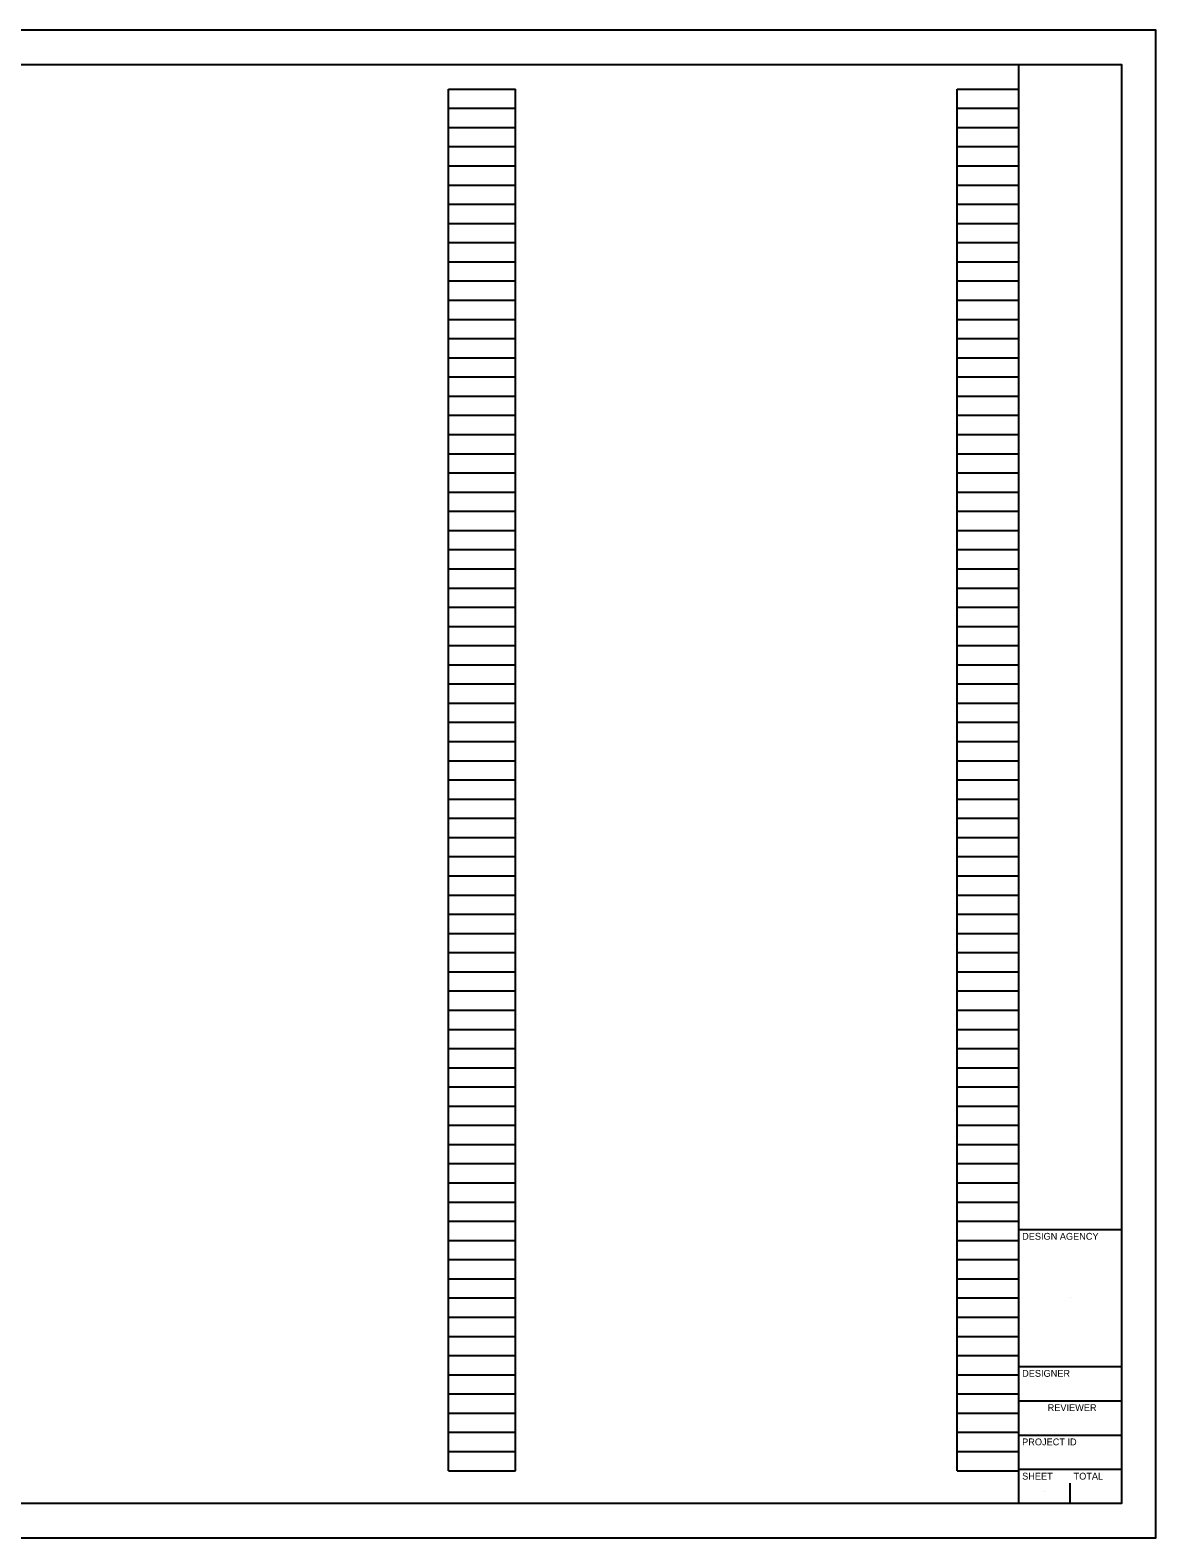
# Model space of a CAD drawing. Extents: x 0 to 34, y 0 to 22.
# Drawn here: x 17.58 to 34, y 0 to 22 of the extents above; entities that cross this region are included whole.
import ezdxf

# ---------------------------------------------------------------- set-up
doc = ezdxf.new("R2010")
doc.units = 0
doc.layers.add('SH_Border', color=7, linetype='Continuous')
doc.layers.add('SH_Data', color=7, linetype='Continuous')

msp = doc.modelspace()

# ---------------------------------------------------------------- linework, layer by layer
at = {"layer": 'SH_Border'}
for p, q in [((32, 0.5), (32, 21.5)), ((32, 4.5), (33.5, 4.5)), ((32, 2.5), (33.5, 2.5)), ((32, 2), (33.5, 2)), ((32, 1.5), (33.5, 1.5)), ((32, 1), (33.5, 1))]:
    msp.add_line(p, q, dxfattribs=at)
msp.add_lwpolyline([(1.5, 21.5), (33.5, 21.5), (33.5, 0.5), (1.5, 0.5)], close=True, dxfattribs=at)
at = {"layer": 'SH_Data'}
for p, q in [((23.68, 0.98), (23.68, 21.14)), ((23.68, 21.14), (24.66, 21.14)), ((24.66, 0.98), (24.66, 21.14)), ((31.1, 0.98), (31.1, 21.14)), ((31.1, 21.14), (32, 21.14)), ((32, 0.98), (32, 21.14)), ((23.68, 20.86), (24.66, 20.86)), ((31.1, 20.86), (32, 20.86)), ((23.68, 20.58), (24.66, 20.58)), ((31.1, 20.58), (32, 20.58)), ((23.68, 20.3), (24.66, 20.3)), ((31.1, 20.3), (32, 20.3)), ((23.68, 20.02), (24.66, 20.02)), ((31.1, 20.02), (32, 20.02)), ((23.68, 19.74), (24.66, 19.74)), ((31.1, 19.74), (32, 19.74)), ((23.68, 19.46), (24.66, 19.46)), ((31.1, 19.46), (32, 19.46)), ((23.68, 19.18), (24.66, 19.18)), ((31.1, 19.18), (32, 19.18)), ((23.68, 18.9), (24.66, 18.9)), ((31.1, 18.9), (32, 18.9)), ((23.68, 18.62), (24.66, 18.62)), ((31.1, 18.62), (32, 18.62)), ((23.68, 18.34), (24.66, 18.34)), ((31.1, 18.34), (32, 18.34)), ((23.68, 18.06), (24.66, 18.06)), ((31.1, 18.06), (32, 18.06)), ((23.68, 17.78), (24.66, 17.78)), ((31.1, 17.78), (32, 17.78)), ((23.68, 17.5), (24.66, 17.5)), ((31.1, 17.5), (32, 17.5)), ((23.68, 17.22), (24.66, 17.22)), ((31.1, 17.22), (32, 17.22)), ((23.68, 16.94), (24.66, 16.94)), ((31.1, 16.94), (32, 16.94)), ((23.68, 16.66), (24.66, 16.66)), ((31.1, 16.66), (32, 16.66)), ((23.68, 16.38), (24.66, 16.38)), ((31.1, 16.38), (32, 16.38)), ((23.68, 16.1), (24.66, 16.1)), ((31.1, 16.1), (32, 16.1)), ((23.68, 15.82), (24.66, 15.82)), ((31.1, 15.82), (32, 15.82)), ((23.68, 15.54), (24.66, 15.54)), ((31.1, 15.54), (32, 15.54)), ((23.68, 15.26), (24.66, 15.26)), ((31.1, 15.26), (32, 15.26)), ((23.68, 14.98), (24.66, 14.98)), ((31.1, 14.98), (32, 14.98)), ((23.68, 14.7), (24.66, 14.7)), ((31.1, 14.7), (32, 14.7)), ((23.68, 14.42), (24.66, 14.42)), ((31.1, 14.42), (32, 14.42)), ((23.68, 14.14), (24.66, 14.14)), ((31.1, 14.14), (32, 14.14)), ((23.68, 13.86), (24.66, 13.86)), ((31.1, 13.86), (32, 13.86)), ((23.68, 13.58), (24.66, 13.58)), ((31.1, 13.58), (32, 13.58)), ((23.68, 13.3), (24.66, 13.3)), ((31.1, 13.3), (32, 13.3)), ((23.68, 13.02), (24.66, 13.02)), ((31.1, 13.02), (32, 13.02)), ((23.68, 12.74), (24.66, 12.74)), ((31.1, 12.74), (32, 12.74)), ((23.68, 12.46), (24.66, 12.46)), ((31.1, 12.46), (32, 12.46)), ((23.68, 12.18), (24.66, 12.18)), ((31.1, 12.18), (32, 12.18)), ((23.68, 11.9), (24.66, 11.9)), ((31.1, 11.9), (32, 11.9)), ((23.68, 11.62), (24.66, 11.62)), ((31.1, 11.62), (32, 11.62)), ((23.68, 11.34), (24.66, 11.34)), ((31.1, 11.34), (32, 11.34)), ((23.68, 11.06), (24.66, 11.06)), ((31.1, 11.06), (32, 11.06)), ((23.68, 10.78), (24.66, 10.78)), ((31.1, 10.78), (32, 10.78)), ((23.68, 10.5), (24.66, 10.5)), ((31.1, 10.5), (32, 10.5)), ((23.68, 10.22), (24.66, 10.22)), ((31.1, 10.22), (32, 10.22)), ((23.68, 9.94), (24.66, 9.94)), ((31.1, 9.94), (32, 9.94)), ((23.68, 9.66), (24.66, 9.66)), ((31.1, 9.66), (32, 9.66)), ((23.68, 9.38), (24.66, 9.38)), ((31.1, 9.38), (32, 9.38)), ((23.68, 9.1), (24.66, 9.1)), ((31.1, 9.1), (32, 9.1)), ((23.68, 8.82), (24.66, 8.82)), ((31.1, 8.82), (32, 8.82)), ((23.68, 8.54), (24.66, 8.54)), ((31.1, 8.54), (32, 8.54)), ((23.68, 8.26), (24.66, 8.26)), ((31.1, 8.26), (32, 8.26)), ((23.68, 7.98), (24.66, 7.98)), ((31.1, 7.98), (32, 7.98)), ((23.68, 7.7), (24.66, 7.7)), ((31.1, 7.7), (32, 7.7)), ((23.68, 7.42), (24.66, 7.42)), ((31.1, 7.42), (32, 7.42)), ((23.68, 7.14), (24.66, 7.14)), ((31.1, 7.14), (32, 7.14)), ((23.68, 6.86), (24.66, 6.86)), ((31.1, 6.86), (32, 6.86)), ((23.68, 6.58), (24.66, 6.58)), ((31.1, 6.58), (32, 6.58)), ((23.68, 6.3), (24.66, 6.3)), ((31.1, 6.3), (32, 6.3)), ((23.68, 6.02), (24.66, 6.02)), ((31.1, 6.02), (32, 6.02)), ((23.68, 5.74), (24.66, 5.74)), ((31.1, 5.74), (32, 5.74)), ((23.68, 5.46), (24.66, 5.46)), ((31.1, 5.46), (32, 5.46)), ((23.68, 5.18), (24.66, 5.18)), ((31.1, 5.18), (32, 5.18)), ((23.68, 4.9), (24.66, 4.9)), ((31.1, 4.9), (32, 4.9)), ((23.68, 4.62), (24.66, 4.62)), ((31.1, 4.62), (32, 4.62)), ((23.68, 4.34), (24.66, 4.34)), ((31.1, 4.34), (32, 4.34)), ((23.68, 4.06), (24.66, 4.06)), ((31.1, 4.06), (32, 4.06)), ((23.68, 3.78), (24.66, 3.78)), ((31.1, 3.78), (32, 3.78)), ((23.68, 3.5), (24.66, 3.5)), ((31.1, 3.5), (32, 3.5)), ((32.75, 3.5), (32.75, 3.5)), ((23.68, 3.22), (24.66, 3.22)), ((31.1, 3.22), (32, 3.22)), ((23.68, 2.94), (24.66, 2.94)), ((31.1, 2.94), (32, 2.94)), ((23.68, 2.66), (24.66, 2.66)), ((31.1, 2.66), (32, 2.66)), ((23.68, 2.38), (24.66, 2.38)), ((31.1, 2.38), (32, 2.38)), ((23.68, 2.1), (24.66, 2.1)), ((31.1, 2.1), (32, 2.1)), ((23.68, 1.82), (24.66, 1.82)), ((31.1, 1.82), (32, 1.82)), ((23.68, 1.54), (24.66, 1.54)), ((31.1, 1.54), (32, 1.54)), ((23.68, 1.26), (24.66, 1.26)), ((31.1, 1.26), (32, 1.26)), ((23.68, 0.98), (24.66, 0.98)), ((31.1, 0.98), (32, 0.98)), ((32.375, 0.675), (32.375, 0.675)), ((32.75, 0.5), (32.75, 0.8))]:
    msp.add_line(p, q, dxfattribs=at)
msp.add_lwpolyline([(0, 0), (34, 0), (34, 22), (0, 22)], close=True, dxfattribs=at)

# ---------------------------------------------------------------- texts
for s, p in [('DESIGN AGENCY', (32.05, 4.35)), ('DESIGNER', (32.05, 2.35)), ('REVIEWER', (32.422, 1.85)), ('PROJECT ID', (32.05, 1.35)), ('SHEET', (32.05, 0.85)), ('TOTAL', (32.8, 0.85))]:
    msp.add_text(s, height=0.1, dxfattribs=at).set_placement(p)

doc.saveas('drawing.dxf')
